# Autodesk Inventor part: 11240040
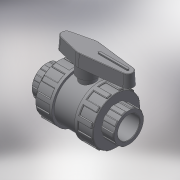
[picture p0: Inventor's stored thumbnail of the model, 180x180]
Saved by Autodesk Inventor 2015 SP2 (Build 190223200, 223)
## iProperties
Created: 2017-11
Part Number: 11240040
Material: Generic
Description: PLASSON BI STOP VALVE CEM PVC 40
Document SubType Name: Modeling
Designer: KIM
Density: 1 g/cm^3
Appearance: Default
Author: KIM
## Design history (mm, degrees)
derived "112400 - 112700.ipt"
feature "Solid1::112400 - 112700.ipt"
tag "TaggingFeature1"
body "Solid1"
other parameters: "d3" = 26, "d4" = 32, "d5" = 18.2, "d7" = 56, "d8" = 72, "d13" = 1.2, "d23" = 26, "d24" = 76.8, "d25" = 0.8, "d26" = 1.2, "d27" = 12, "d28" = 6, "d29" = 19.5, "d30" = 0, "d35" = 1.2, "d45" = 360 deg, "d47" = 0.8, "d50" = 44, "d51" = 24, "d53" = 0, "d55" = 8, "d56" = 4, "d57" = 18.2, "d58" = 0, "d59" = 1.2, "d61" = 360 deg, "d63" = 32, "d64" = 74, "d66" = 96, "d68" = 16, "d69" = 28.8, "d70" = 18.5, "d71" = 3 deg, "d73" = 1.6, "d74" = 38.4, "d75" = 2.22, "d76" = 0, "d77" = 0.8, "l_" = 26, "F_" = 74, "J_" = 96, "d67" = 32, "d72" = 8
